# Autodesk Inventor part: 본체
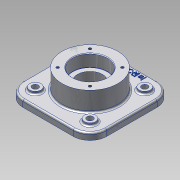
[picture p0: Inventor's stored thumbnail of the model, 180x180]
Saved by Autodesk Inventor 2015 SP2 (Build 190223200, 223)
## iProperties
Created: 2015-07
Part Number: 본체
Material: 알루미늄 6061
Document SubType Name: Modeling
Designer: AMC
Density: 2.7 g/cm^3
Appearance: 알루미늄 - 평지
Mass: 1459.27 g
Surface Area: 800.934 cm^2
Volume: 540.471 cm^3
Author: AMC
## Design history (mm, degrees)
sketch "스케치1"
  geometry: L1 (-75, -75)-(75, -75); L2 (75, -75)-(75, 75); L3 (75, 75)-(-75, 75); L4 (-75, 75)-(-75, -75); L5 (-75, -75)-(75, 75); L6 (75, -75)-(-75, 75); 1 further point
  constraints: 12 end point, 2 midpoint, 2 parallel, 1 horizontal, 1 perpendicular
  dimensions: "d0" = 150 distance of L3.end L2.end; "d1" = 150 distance of L2.end L1.end
extrude "돌출1" new body sketch "스케치1" distance "d2" = 12; taper "d3" = 0 deg
sketch "스케치2"
  geometry: C1 r 50 at (0, 0); 1 further point
  constraints: 1 centre point, 1 coincident
  dimensions: "d4" = 100 diameter of C1
extrude "돌출2" join sketch "스케치2" distance "d5" = 47; taper "d7" = 0 deg; dims "d6" = 23, "d8" = 0
sketch "스케치3"
  geometry: C1 r 10 at (-49, -49); C2 r 10 at (49, -49); C3 r 10 at (49, 49); C4 r 10 at (-49, 49); 1 further point
  constraints: 4 centre point, 3 equal radius, 2 horizontal alignment, 2 vertical alignment
  dimensions: "d9" = 20 diameter of C1; "d10" = 49 horizontal distance of C1.centre point (0, 0); "d11" = 98 distance of C1.centre C4.centre; "d12" = 98 distance of C2.centre C1.centre; "d13" = 49 horizontal distance of point (0, 0) C1.centre
extrude "돌출3" join sketch "스케치3" distance "d14" = 5; taper "d15" = 0 deg
fillet "모깎기1" dims "d16" = 30
hole "구멍1" diameter "d19" = 45; stored, may be unused: countersink angle "d23" = 90 deg, drill point angle "d25" = 118 deg; dims "d17" = 10, "d18" = 10, "d20" = 6, "d21" = 62, "d22" = 22, "d24" = 8
hole "구멍2" diameter "d28" = 62; stored, may be unused: countersink angle "d32" = 90 deg, drill point angle "d34" = 0 deg; dims "d26" = 10, "d27" = 10, "d29" = 6, "d30" = 62, "d31" = 22, "d33" = 22
hole "구멍3" diameter "d37" = 11; stored, may be unused: countersink angle "d41" = 90 deg, drill point angle "d43" = 118 deg; dims "d35" = 10, "d36" = 10, "d38" = 124, "d39" = 62, "d40" = 22, "d42" = 140.8
hole "구멍4" diameter "d46" = 11; stored, may be unused: countersink angle "d50" = 90 deg, drill point angle "d52" = 118 deg; dims "d44" = 10, "d45" = 10, "d47" = 124, "d48" = 62, "d49" = 22, "d51" = 140.8
hole "구멍5" diameter "d55" = 11; stored, may be unused: countersink angle "d59" = 90 deg, drill point angle "d61" = 118 deg; dims "d53" = 10, "d54" = 10, "d56" = 124, "d57" = 62, "d58" = 22, "d60" = 140.8
hole "구멍6" diameter "d64" = 11; stored, may be unused: countersink angle "d68" = 90 deg, drill point angle "d70" = 118 deg; dims "d62" = 10, "d63" = 10, "d65" = 124, "d66" = 62, "d67" = 22, "d69" = 140.8
fillet "모깎기2" dims "d71" = 3
chamfer "모따기1" distance "d72" = 1; stored, may be unused: second distance "d73" = 2, angle "d74" = 45 deg
fillet "모깎기3" dims "d75" = 0.3
sketch "스케치4"
  geometry: L1 (0, 0)-(0, 41); L2 (0, 0)-(-28.991, 28.991); A1 r 41 centre (0, 0) between (0, 41) and (-28.991, 28.991); 2 further points
  constraints: 4 end point, 2 coincident, 2 point on circle, 1 centre point, 1 vertical
  dimensions: "d76" = 82 diameter of A1; "d77" = 45 deg angle of L1 L2
hole "구멍7" sketch "스케치4" at (-28.991, 28.991) diameter "d78" = 4.917; stored, may be unused: countersink angle "d82" = 90 deg, drill point angle "d84" = 118 deg; dims "d79" = 10, "d80" = 62, "d81" = 22, "d83" = 13
sketch "스케치5"
  geometry: L1 (0, 0)-(0, -41); L2 (0, 0)-(28.991, -28.991); A1 r 41 centre (0, 0) between (0, -41) and (28.991, -28.991); 2 further points
  constraints: 4 end point, 2 coincident, 2 point on circle, 1 centre point, 1 vertical
  dimensions: "d85" = 82 diameter of A1; "d86" = 45 deg angle of L1 L2
hole "구멍8" sketch "스케치5" at (28.991, -28.991) diameter "d87" = 4.917; stored, may be unused: countersink angle "d91" = 90 deg, drill point angle "d93" = 118 deg; dims "d88" = 10, "d89" = 62, "d90" = 22, "d92" = 13
sketch "스케치6"
  geometry: 2 further points
  constraints: 1 vertical alignment, 1 other
  dimensions: "d97" = 65 distance of point (0, 0) point (0, 65)
feature "엠보싱1" sketch "스케치6" dims "d98" = 1, "d99" = 0
node "솔리드1"
pattern_circular "원형 패턴1" dims angle "d95" = 360 deg
